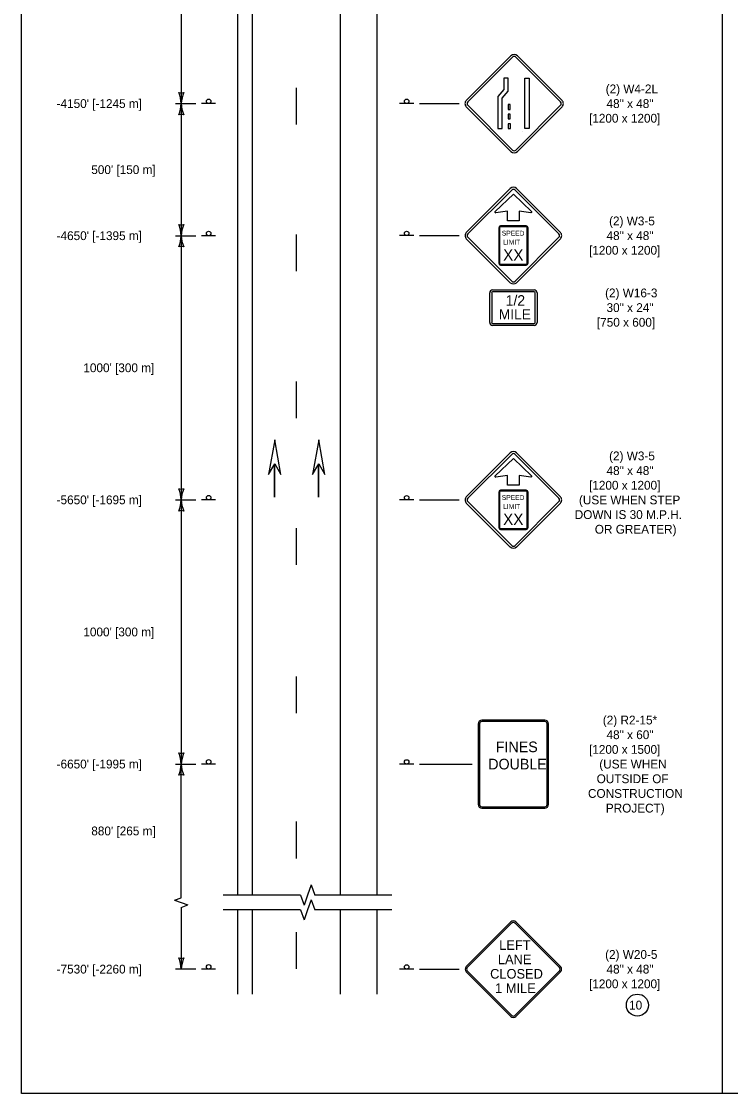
# Model space of a CAD drawing. Extents: x 49991.4 to 50021, y 49987.6 to 50011.4.
# Drawn here: x 49999.38 to 50004.22, y 49987.8 to 49995.1 of the extents above; entities that cross this region are included whole.
import ezdxf

# ---------------------------------------------------------------- set-up
doc = ezdxf.new("R2010")
doc.units = 0
for name, color, linetype in [('Level 1', 7, 'Continuous'), ('Level 2', 7, 'Continuous'), ('Level 25', 7, 'Continuous'), ('Level 3', 7, 'Continuous'), ('Level 6', 7, 'Continuous')]:
    doc.layers.add(name, color=color, linetype=linetype)

msp = doc.modelspace()

# ---------------------------------------------------------------- linework, layer by layer
at = {"layer": 'Level 1'}
for p, q in [((50000.8598, 49989.1514), (50000.8598, 49995.7676)), ((50000.9598, 49989.1514), (50000.9598, 49995.7676)), ((50001.5598, 49989.1514), (50001.5598, 49995.7676)), ((50001.8098, 49989.1514), (50001.8098, 49995.7676)), ((50001.2598, 49994.4014), (50001.2598, 49994.6514)), ((50000.7078, 49994.5441), (50000.6118, 49994.5441)), ((50002.0578, 49994.5441), (50001.9618, 49994.5441)), ((50002.4167, 49993.6658), (50002.716, 49993.9651)), ((50002.4268, 49993.6557), (50002.7261, 49993.955)), ((50002.7487, 49993.955), (50003.048, 49993.6557)), ((50002.7487, 49993.955), (50002.7487, 49993.955)), ((50002.7588, 49993.9651), (50003.0581, 49993.6658)), ((50002.7588, 49993.9651), (50002.7588, 49993.9651)), ((50002.613, 49993.8094), (50002.7374, 49993.9267)), ((50002.7374, 49993.9267), (50002.8618, 49993.8094)), ((50002.6971, 49993.8107), (50002.6171, 49993.8007)), ((50002.6971, 49993.7452), (50002.6971, 49993.8107)), ((50002.7777, 49993.8107), (50002.7777, 49993.7452)), ((50002.8577, 49993.8007), (50002.7777, 49993.8107)), ((50002.7777, 49993.7452), (50002.6971, 49993.7452)), ((50002.6381, 49993.6977), (50002.6381, 49993.4564)), ((50002.6433, 49993.6977), (50002.6433, 49993.4564)), ((50002.8253, 49993.7102), (50002.6505, 49993.7102)), ((50002.8253, 49993.705), (50002.6505, 49993.705)), ((50002.7379, 49993.7102), (50002.7379, 49993.7102)), ((50002.8326, 49993.4564), (50002.8326, 49993.6977)), ((50002.8378, 49993.4564), (50002.8378, 49993.6977)), ((50000.7078, 49993.644), (50000.6118, 49993.644)), ((50001.2598, 49993.4014), (50001.2598, 49993.6514)), ((50002.0578, 49993.6444), (50001.9618, 49993.6444)), ((50002.716, 49993.3238), (50002.4167, 49993.6231)), ((50002.7261, 49993.3338), (50002.4268, 49993.6331)), ((50003.048, 49993.6331), (50002.7487, 49993.3338)), ((50003.0581, 49993.6231), (50002.7588, 49993.3238)), ((50002.6505, 49993.4491), (50002.8253, 49993.4491)), ((50002.6505, 49993.4439), (50002.8253, 49993.4439)), ((50002.5761, 49993.0531), (50002.5761, 49993.2547)), ((50002.5896, 49993.2547), (50002.5896, 49993.0531)), ((50002.5963, 49993.2749), (50002.8785, 49993.2749)), ((50002.8785, 49993.2615), (50002.5963, 49993.2615)), ((50002.8852, 49993.0531), (50002.8852, 49993.2547)), ((50002.8987, 49993.2547), (50002.8987, 49993.0531)), ((50002.5963, 49993.0464), (50002.8785, 49993.0464)), ((50002.8785, 49993.033), (50002.5963, 49993.033)), ((50001.2598, 49992.4014), (50001.2598, 49992.6514)), ((50002.4167, 49991.8648), (50002.716, 49992.1641)), ((50002.4268, 49991.8547), (50002.7261, 49992.154)), ((50002.7487, 49992.154), (50003.048, 49991.8547)), ((50002.7487, 49992.154), (50002.7487, 49992.154)), ((50002.7588, 49992.1641), (50003.0581, 49991.8648)), ((50002.7588, 49992.1641), (50002.7588, 49992.1641)), ((50001.1098, 49991.8627), (50001.1098, 49992.0887)), ((50001.1101, 49991.8627), (50001.1101, 49992.0887)), ((50001.4098, 49991.8627), (50001.4098, 49992.0887)), ((50001.4101, 49991.8627), (50001.4101, 49992.0887)), ((50002.613, 49992.0084), (50002.7374, 49992.1257)), ((50002.7374, 49992.1257), (50002.8618, 49992.0084)), ((50002.6971, 49992.0098), (50002.6171, 49991.9997)), ((50002.6971, 49991.9443), (50002.6971, 49992.0098)), ((50002.7777, 49992.0098), (50002.7777, 49991.9443)), ((50002.8577, 49991.9997), (50002.7777, 49992.0098)), ((50002.8253, 49991.9092), (50002.6505, 49991.9092)), ((50002.7777, 49991.9443), (50002.6971, 49991.9443)), ((50002.7379, 49991.9092), (50002.7379, 49991.9092)), ((50000.7078, 49991.844), (50000.6118, 49991.844)), ((50002.0578, 49991.8434), (50001.9618, 49991.8434)), ((50002.6381, 49991.8967), (50002.6381, 49991.6554)), ((50002.6433, 49991.8967), (50002.6433, 49991.6554)), ((50002.8253, 49991.904), (50002.6505, 49991.904)), ((50002.8326, 49991.6554), (50002.8326, 49991.8967)), ((50002.8378, 49991.6554), (50002.8378, 49991.8967)), ((50002.716, 49991.5228), (50002.4167, 49991.8221)), ((50002.7261, 49991.5329), (50002.4268, 49991.8322)), ((50003.048, 49991.8322), (50002.7487, 49991.5329)), ((50003.0581, 49991.8221), (50002.7588, 49991.5228)), ((50001.2598, 49991.4014), (50001.2598, 49991.6514)), ((50002.6505, 49991.6481), (50002.8253, 49991.6481)), ((50002.6505, 49991.6429), (50002.8253, 49991.6429)), ((50001.2598, 49990.3906), (50001.2598, 49990.6406)), ((50002.4974, 49990.3184), (50002.4974, 49989.7684)), ((50002.5074, 49990.3184), (50002.5074, 49989.7684)), ((50002.9524, 49990.3434), (50002.5224, 49990.3434)), ((50002.9524, 49990.3334), (50002.5224, 49990.3334)), ((50002.9674, 49989.7684), (50002.9674, 49990.3184)), ((50002.9774, 49989.7684), (50002.9774, 49990.3184)), ((50000.7078, 49990.044), (50000.6118, 49990.044)), ((50002.0578, 49990.0434), (50001.9618, 49990.0434)), ((50002.5224, 49989.7534), (50002.9524, 49989.7534)), ((50002.5224, 49989.7434), (50002.9524, 49989.7434)), ((50001.2598, 49989.4014), (50001.2598, 49989.6514)), ((50000.8598, 49988.4756), (50000.8598, 49989.0514)), ((50000.9598, 49988.4756), (50000.9598, 49989.0514)), ((50001.5598, 49988.4756), (50001.5598, 49989.0514)), ((50001.8098, 49988.4756), (50001.8098, 49989.0514)), ((50002.4157, 49988.664), (50002.7198, 49988.968)), ((50002.4228, 49988.6569), (50002.7268, 49988.961)), ((50002.7481, 49988.961), (50003.0521, 49988.6569)), ((50002.7551, 49988.968), (50003.0592, 49988.664)), ((50001.2598, 49988.6478), (50001.2598, 49988.8978)), ((50000.7078, 49988.6467), (50000.6118, 49988.6467)), ((50002.0578, 49988.6463), (50001.9618, 49988.6463)), ((50002.7198, 49988.3246), (50002.4157, 49988.6286)), ((50002.7268, 49988.3316), (50002.4228, 49988.6357)), ((50003.0521, 49988.6357), (50002.7481, 49988.3316)), ((50003.0592, 49988.6286), (50002.7551, 49988.3246))]:
    msp.add_line(p, q, dxfattribs=at)
for points in [[(49999.3835, 49998.9992), (50016.7501, 49998.9992), (50016.7501, 49987.7988), (49999.3835, 49987.7988)], [(50001.1518, 49992.0163), (50001.1101, 49992.2529), (50001.0682, 49992.0163), (50001.1101, 49992.0885)], [(50001.4518, 49992.0163), (50001.4101, 49992.2529), (50001.3682, 49992.0163), (50001.4101, 49992.0885)]]:
    msp.add_lwpolyline(points, close=True, dxfattribs=at)
for centre in [(50000.6598, 49994.5593), (50002.0098, 49994.5593), (50000.6598, 49993.6592), (50002.0098, 49993.6596), (50000.6598, 49991.8592), (50002.0098, 49991.8586), (50000.6598, 49990.0592), (50002.0098, 49990.0586), (50000.6598, 49988.6619), (50002.0098, 49988.6615)]:
    msp.add_circle(centre, 0.0152, dxfattribs=at)
for centre, radius, start, end in [((50002.7374, 49993.9437), 0.0302, 45.00007, 134.99993), ((50002.7374, 49993.9437), 0.016, 45.00007, 134.99993), ((50002.6166, 49993.8058), 0.00509, 134.83509, 275.61741), ((50002.8583, 49993.8058), 0.00508, 264.17053, 45.37126), ((50002.4381, 49993.6444), 0.0302, 134.99992, 225.00007), ((50002.6505, 49993.6977), 0.0125, 90, 180), ((50002.6505, 49993.6977), 0.00728, 90, 180), ((50002.8253, 49993.6977), 0.0125, 0, 90), ((50002.8253, 49993.6977), 0.00728, 0, 90), ((50003.0367, 49993.6444), 0.0302, 314.99992, 45.00007), ((50002.4381, 49993.6444), 0.016, 134.99993, 225.00007), ((50003.0367, 49993.6444), 0.016, 314.99992, 45.00007), ((50002.6505, 49993.4564), 0.0125, 180, 270), ((50002.6505, 49993.4564), 0.00728, 180, 270), ((50002.8253, 49993.4564), 0.00728, 270, 0), ((50002.8253, 49993.4564), 0.0125, 270, 0), ((50002.7374, 49993.3451), 0.0302, 225.00007, 314.99993), ((50002.7374, 49993.3451), 0.016, 225.00007, 314.99993), ((50002.5963, 49993.2547), 0.0202, 90, 180), ((50002.5963, 49993.2547), 0.00672, 90, 180), ((50002.8785, 49993.2547), 0.0202, 0, 90), ((50002.8785, 49993.2547), 0.00672, 0, 90), ((50002.5963, 49993.0531), 0.0202, 180, 270), ((50002.5963, 49993.0531), 0.00672, 180, 270), ((50002.8785, 49993.0531), 0.00672, 270, 0), ((50002.8785, 49993.0531), 0.0202, 270, 0), ((50002.7374, 49992.1428), 0.0302, 45.00007, 134.99993), ((50002.7374, 49992.1428), 0.016, 45.00007, 134.99993), ((50002.6166, 49992.0048), 0.00509, 134.83509, 275.61741), ((50002.8583, 49992.0048), 0.00508, 264.17053, 45.37126), ((50002.6505, 49991.8967), 0.0125, 90, 180), ((50002.8253, 49991.8967), 0.0125, 0, 90), ((50002.4381, 49991.8435), 0.0302, 134.99992, 225.00007), ((50002.4381, 49991.8435), 0.016, 134.99993, 225.00007), ((50002.6505, 49991.8967), 0.00728, 90, 180), ((50002.8253, 49991.8967), 0.00728, 0, 90), ((50003.0367, 49991.8435), 0.016, 314.99992, 45.00007), ((50003.0367, 49991.8435), 0.0302, 314.99992, 45.00007), ((50002.6505, 49991.6554), 0.0125, 180, 270), ((50002.6505, 49991.6554), 0.00728, 180, 270), ((50002.8253, 49991.6554), 0.00728, 270, 0), ((50002.8253, 49991.6554), 0.0125, 270, 0), ((50002.7374, 49991.5442), 0.0302, 225.00007, 314.99993), ((50002.7374, 49991.5442), 0.016, 225.00007, 314.99993), ((50002.5224, 49990.3184), 0.025, 90, 180), ((50002.5224, 49990.3184), 0.015, 90, 180), ((50002.9524, 49990.3184), 0.025, 0, 90), ((50002.9524, 49990.3184), 0.015, 0, 90), ((50002.5224, 49989.7684), 0.025, 180, 270), ((50002.5224, 49989.7684), 0.015, 180, 270), ((50002.9524, 49989.7684), 0.025, 270, 0), ((50002.9524, 49989.7684), 0.015, 270, 0), ((50002.7374, 49988.9503), 0.025, 45, 135), ((50002.7374, 49988.9503), 0.015, 45, 135), ((50002.4333, 49988.6463), 0.025, 134.99976, 225), ((50002.4333, 49988.6463), 0.015, 134.99976, 225), ((50003.0415, 49988.6463), 0.015, 315, 45), ((50003.0415, 49988.6463), 0.025, 315, 45), ((50002.7374, 49988.3422), 0.015, 225.00043, 315), ((50002.7374, 49988.3422), 0.025, 225.00043, 315)]:
    msp.add_arc(centre, radius, start, end, dxfattribs=at)
at = {"layer": 'Level 2'}
for p, q in [((50002.7018, 49994.7176), (50002.6733, 49994.7176)), ((50002.6733, 49994.7176), (50002.6733, 49994.6393)), ((50002.7018, 49994.6288), (50002.7018, 49994.7176)), ((50002.6733, 49994.6393), (50002.6326, 49994.592)), ((50002.6611, 49994.5814), (50002.7018, 49994.6288)), ((50002.6326, 49994.592), (50002.6326, 49994.374)), ((50002.6611, 49994.374), (50002.6611, 49994.5814)), ((50002.7167, 49994.5371), (50002.7016, 49994.5371)), ((50002.7016, 49994.5371), (50002.7016, 49994.5045)), ((50002.7016, 49994.5045), (50002.7167, 49994.5045)), ((50002.7167, 49994.4718), (50002.7016, 49994.4718)), ((50002.7016, 49994.4718), (50002.7016, 49994.4392)), ((50002.7167, 49994.5045), (50002.7167, 49994.5371)), ((50002.7167, 49994.4392), (50002.7167, 49994.4718)), ((50002.7016, 49994.4392), (50002.7167, 49994.4392)), ((50002.7171, 49994.4066), (50002.702, 49994.4066)), ((50002.702, 49994.4066), (50002.702, 49994.374)), ((50002.7171, 49994.374), (50002.7171, 49994.4066)), ((50002.6326, 49994.374), (50002.6611, 49994.374)), ((50002.702, 49994.374), (50002.7171, 49994.374))]:
    msp.add_line(p, q, dxfattribs=at)
msp.add_circle((50003.5834, 49988.4014), 0.075, dxfattribs=at)
at = {"layer": 'Level 25'}
for p, q in [((50002.7212, 49994.8705), (50002.4164, 49994.5658)), ((50002.4267, 49994.5555), (50002.7314, 49994.8603)), ((50002.7544, 49994.8603), (50003.0591, 49994.5555)), ((50002.7544, 49994.8603), (50002.7544, 49994.8603)), ((50003.0694, 49994.5658), (50002.7647, 49994.8705)), ((50002.8167, 49994.374), (50002.8167, 49994.7176)), ((50002.8167, 49994.7176), (50002.8452, 49994.7176)), ((50002.8452, 49994.7176), (50002.8452, 49994.374)), ((50002.4164, 49994.5223), (50002.7212, 49994.2176)), ((50002.7314, 49994.2278), (50002.4267, 49994.5326)), ((50003.0591, 49994.5326), (50002.7544, 49994.2278)), ((50002.7647, 49994.2176), (50003.0694, 49994.5223)), ((50002.8452, 49994.374), (50002.8167, 49994.374))]:
    msp.add_line(p, q, dxfattribs=at)
msp.add_lwpolyline([(50002.7979, 49994.3525), (50002.7976, 49994.3527)], dxfattribs=at)
for centre, radius, start, end in [((50002.7429, 49994.8488), 0.0308, 45.00007, 134.99993), ((50002.7429, 49994.8488), 0.0162, 45.00007, 134.99993), ((50002.4382, 49994.5441), 0.0308, 134.99992, 225.00007), ((50002.4382, 49994.5441), 0.0162, 134.99993, 225.00007), ((50003.0476, 49994.5441), 0.0162, 314.99992, 45.00007), ((50003.0476, 49994.5441), 0.0308, 314.99992, 45.00007), ((50002.7429, 49994.2393), 0.0308, 225.00007, 314.99993), ((50002.7429, 49994.2393), 0.0162, 225.00007, 314.99993)]:
    msp.add_arc(centre, radius, start, end, dxfattribs=at)
at = {"layer": 'Level 3'}
for p, q in [((50004.1614, 49998.9992), (50004.1614, 49987.7988)), ((50000.4732, 49996.128), (50000.4732, 49994.544)), ((50000.4332, 49994.544), (50000.5718, 49994.544)), ((50000.4732, 49994.544), (50000.4729, 49993.644)), ((50002.0978, 49994.5441), (50002.3677, 49994.5441)), ((50000.4332, 49993.644), (50000.5718, 49993.644)), ((50000.4729, 49993.644), (50000.4729, 49991.844)), ((50002.0978, 49993.6444), (50002.3679, 49993.6444)), ((50000.4332, 49991.844), (50000.5718, 49991.844)), ((50000.4729, 49991.844), (50000.4732, 49990.044)), ((50002.0978, 49991.8434), (50002.3679, 49991.8434)), ((50000.4332, 49990.044), (50000.5718, 49990.044)), ((50000.4732, 49989.1323), (50000.4732, 49990.044)), ((50002.0978, 49990.0434), (50002.4574, 49990.0434)), ((50000.4275, 49989.1161), (50000.4732, 49989.1323)), ((50000.4275, 49989.1161), (50000.4732, 49989.0999)), ((50000.4732, 49989.0999), (50000.5189, 49989.0837)), ((50000.4732, 49989.0675), (50000.5189, 49989.0837)), ((50000.4732, 49989.0675), (50000.4732, 49988.6467)), ((50000.5718, 49988.6467), (50000.4332, 49988.6467)), ((50002.0978, 49988.6463), (50002.3683, 49988.6463))]:
    msp.add_line(p, q, dxfattribs=at)
for centre, radius, start, end in [((50000.251, 49994.5348), 0.2223, 2.36048, 22.54399), ((50000.4732, 49994.6722), 0.0548, 252.13882, 287.86118), ((50000.7059, 49994.5325), 0.233, 157.92284, 177.17269), ((50000.2405, 49994.5555), 0.233, 337.92284, 357.17269), ((50000.6953, 49994.5532), 0.2223, 182.36048, 202.54399), ((50000.4732, 49994.4158), 0.0548, 72.13882, 107.86118), ((50000.2508, 49993.6348), 0.2223, 2.36048, 22.54399), ((50000.4729, 49993.7722), 0.0548, 252.13882, 287.86118), ((50000.7056, 49993.6325), 0.233, 157.92284, 177.17269), ((50000.2402, 49993.6555), 0.233, 337.92284, 357.17269), ((50000.695, 49993.6532), 0.2223, 182.36048, 202.54399), ((50000.4729, 49993.5158), 0.0548, 72.13882, 107.86118), ((50000.2508, 49991.8348), 0.2223, 2.36048, 22.54399), ((50000.4729, 49991.9722), 0.0548, 252.13882, 287.86118), ((50000.7056, 49991.8325), 0.233, 157.92284, 177.17269), ((50000.2402, 49991.8555), 0.233, 337.92284, 357.17269), ((50000.695, 49991.8532), 0.2223, 182.36048, 202.54399), ((50000.4729, 49991.7158), 0.0548, 72.13882, 107.86118), ((50000.251, 49990.0348), 0.2223, 2.36048, 22.54399), ((50000.4732, 49990.1722), 0.0548, 252.13882, 287.86118), ((50000.7059, 49990.0325), 0.233, 157.92284, 177.17269), ((50000.2405, 49990.0555), 0.233, 337.92284, 357.17269), ((50000.6953, 49990.0532), 0.2223, 182.36048, 202.54399), ((50000.4732, 49989.9158), 0.0548, 72.13882, 107.86118), ((50000.251, 49988.6375), 0.2223, 2.36048, 22.54399), ((50000.4732, 49988.7749), 0.0548, 252.13882, 287.86118), ((50000.7059, 49988.6352), 0.233, 157.92284, 177.17269)]:
    msp.add_arc(centre, radius, start, end, dxfattribs=at)
at = {"layer": 'Level 6'}
for p, q in [((50001.3591, 49989.2199), (50001.3348, 49989.1514)), ((50001.3591, 49989.2199), (50001.3834, 49989.1514)), ((50001.2862, 49989.1514), (50000.7598, 49989.1514)), ((50001.2862, 49989.1514), (50001.3105, 49989.0829)), ((50001.3348, 49989.1514), (50001.3105, 49989.0829)), ((50001.9098, 49989.1514), (50001.3834, 49989.1514)), ((50001.3591, 49989.1199), (50001.3348, 49989.0514)), ((50001.3591, 49989.1199), (50001.3834, 49989.0514)), ((50001.2862, 49989.0514), (50000.7598, 49989.0514)), ((50001.2862, 49989.0514), (50001.3105, 49988.9829)), ((50001.3348, 49989.0514), (50001.3105, 49988.9829)), ((50001.9098, 49989.0514), (50001.3834, 49989.0514))]:
    msp.add_line(p, q, dxfattribs=at)

# ---------------------------------------------------------------- texts
at = {"layer": 'Level 1'}
for s, height, p in [('SPEED', 0.03301, (50002.6587, 49993.6445)), ('LIMIT', 0.03301, (50002.6677, 49993.5835)), ('XX', 0.07775, (50002.6676, 49993.474)), ('SPEED', 0.03301, (50002.6587, 49991.8435)), ('LIMIT', 0.03301, (50002.6677, 49991.7825)), ('XX', 0.07775, (50002.6676, 49991.673)), ('FINES', 0.0725, (50002.618, 49990.1249)), ('DOUBLE', 0.0725, (50002.5665, 49990.0074)), ('LEFT', 0.06543, (50002.6413, 49988.7779)), ('LANE', 0.06543, (50002.6319, 49988.68)), ('CLOSED', 0.06543, (50002.5791, 49988.5821)), ('1 MILE', 0.06543, (50002.6131, 49988.4841))]:
    msp.add_text(s, height=height, dxfattribs=at).set_placement(p)
for s, height, p in [('1/2', 0.07124, (50002.685, 49993.1674)), ('MILE', 0.06989, (50002.6387, 49993.0733))]:
    msp.add_text(s, height=height, rotation=360, dxfattribs=at).set_placement(p)
at = {"layer": 'Level 2'}
for s, p in [('(2) W4-2L', (50003.3669, 49994.6141)), ("-4150' [-1245 m]", (49999.6235, 49994.514)), ('48" x 48"', (50003.3728, 49994.5141)), ('[1200 x 1200]', (50003.2533, 49994.4141)), ("500' [150 m]", (49999.8597, 49994.064)), ('(2) W3-5', (50003.3901, 49993.7144)), ("-4650' [-1395 m]", (49999.6235, 49993.614)), ('48" x 48"', (50003.3728, 49993.6144)), ('[1200 x 1200]', (50003.2533, 49993.5144)), ('(2) W16-3', (50003.3629, 49993.2239)), ('30" x 24"', (50003.3728, 49993.1239)), ('[750 x 600]', (50003.3072, 49993.0239)), ("1000' [300 m]", (49999.8057, 49992.714)), ('(2) W3-5', (50003.3902, 49992.1135)), ('48" x 48"', (50003.3729, 49992.0135)), ('[1200 x 1200]', (50003.2535, 49991.9135)), ("-5650' [-1695 m]", (49999.6235, 49991.814)), ('(USE WHEN STEP', (50003.1848, 49991.8135)), ('DOWN IS 30 M.P.H.', (50003.156, 49991.7135)), ('OR GREATER)', (50003.2927, 49991.6135)), ("1000' [300 m]", (49999.8058, 49990.914)), ('(2) R2-15*', (50003.3476, 49990.3137)), ('48" x 60"', (50003.3728, 49990.2137)), ('[1200 x 1500]', (50003.2533, 49990.1137)), ("-6650' [-1995 m]", (49999.6235, 49990.014)), ('(USE WHEN', (50003.3235, 49990.0137)), ('OUTSIDE OF', (50003.3055, 49989.9137)), ('CONSTRUCTION', (50003.2463, 49989.8137)), ('PROJECT)', (50003.368, 49989.7137)), ("880' [265 m]", (49999.8598, 49989.5582)), ('(2) W20-5', (50003.3632, 49988.7164)), ("-7530' [-2260 m]", (49999.6235, 49988.6167)), ('48" x 48"', (50003.3728, 49988.6164)), ('[1200 x 1200]', (50003.2533, 49988.5164)), ('10', (50003.5266, 49988.3714))]:
    msp.add_text(s, height=0.06, dxfattribs=at).set_placement(p)

doc.saveas('drawing.dxf')
